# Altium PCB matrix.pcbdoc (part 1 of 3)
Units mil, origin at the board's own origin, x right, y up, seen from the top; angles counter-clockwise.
Board outline 9450 x 9250 mil, 2 copper layers (Top Layer, Bottom Layer); 316 components, 228 nets, 906 pads, 1393 vias.
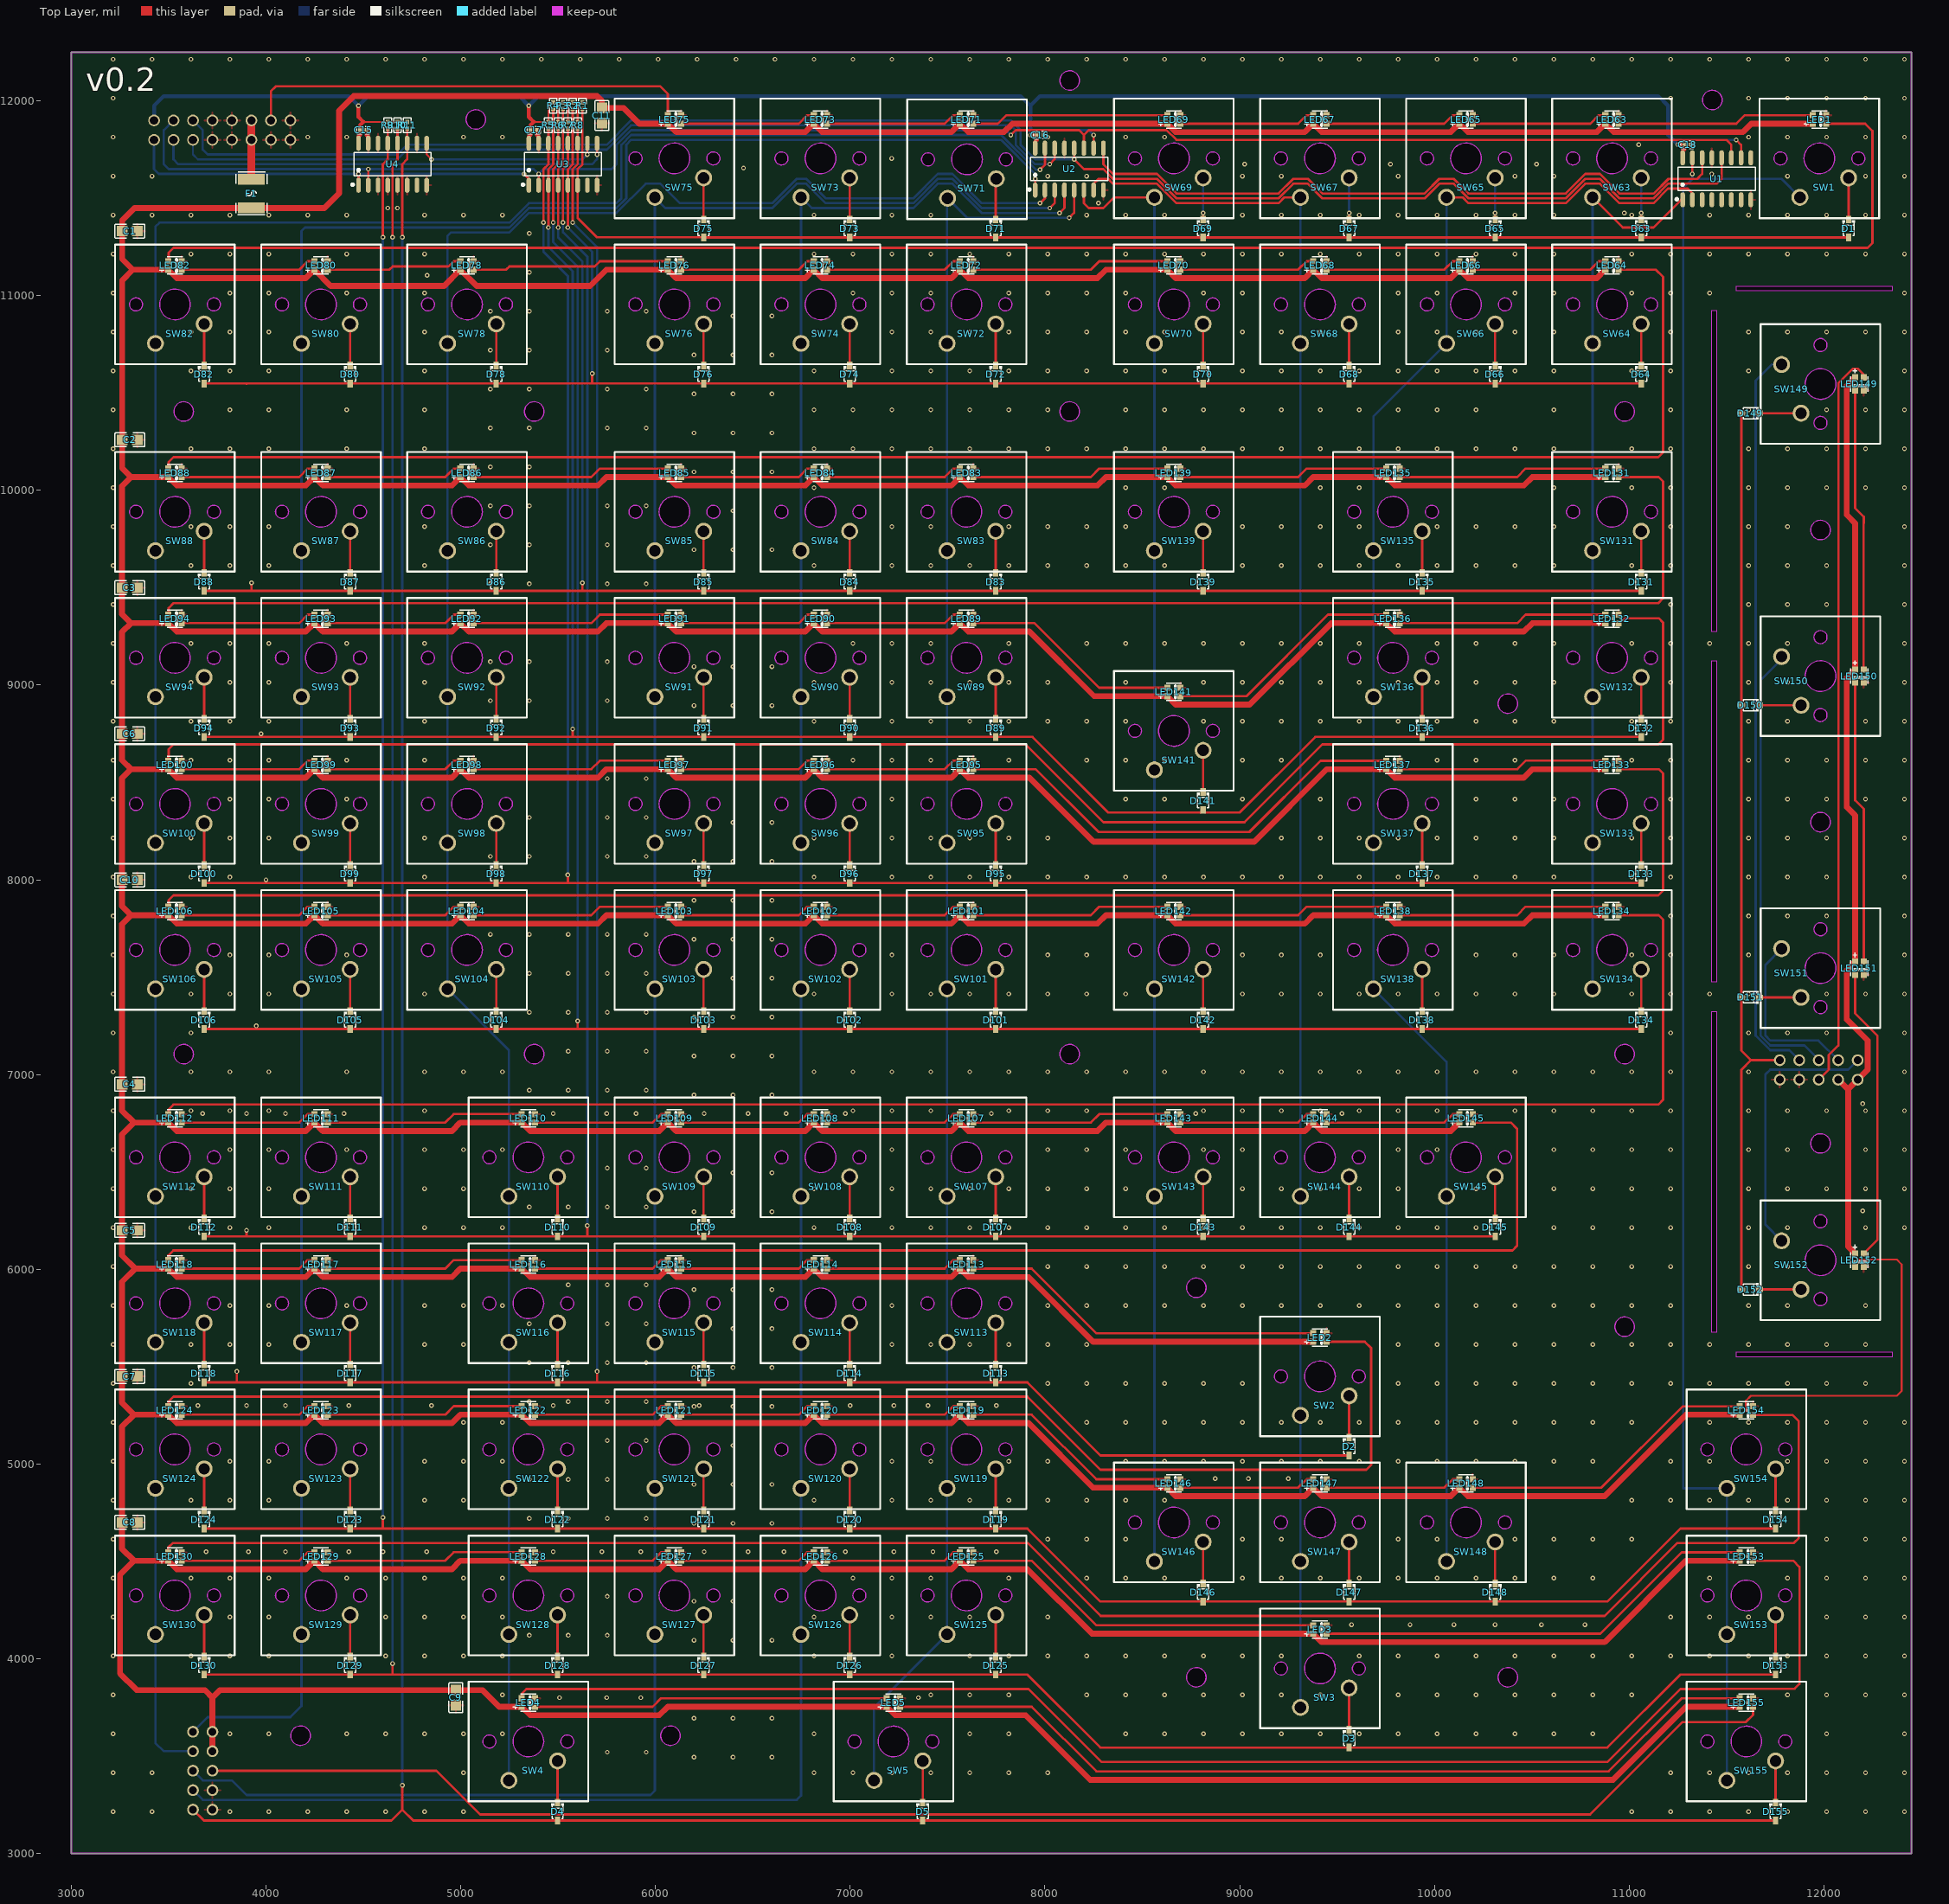
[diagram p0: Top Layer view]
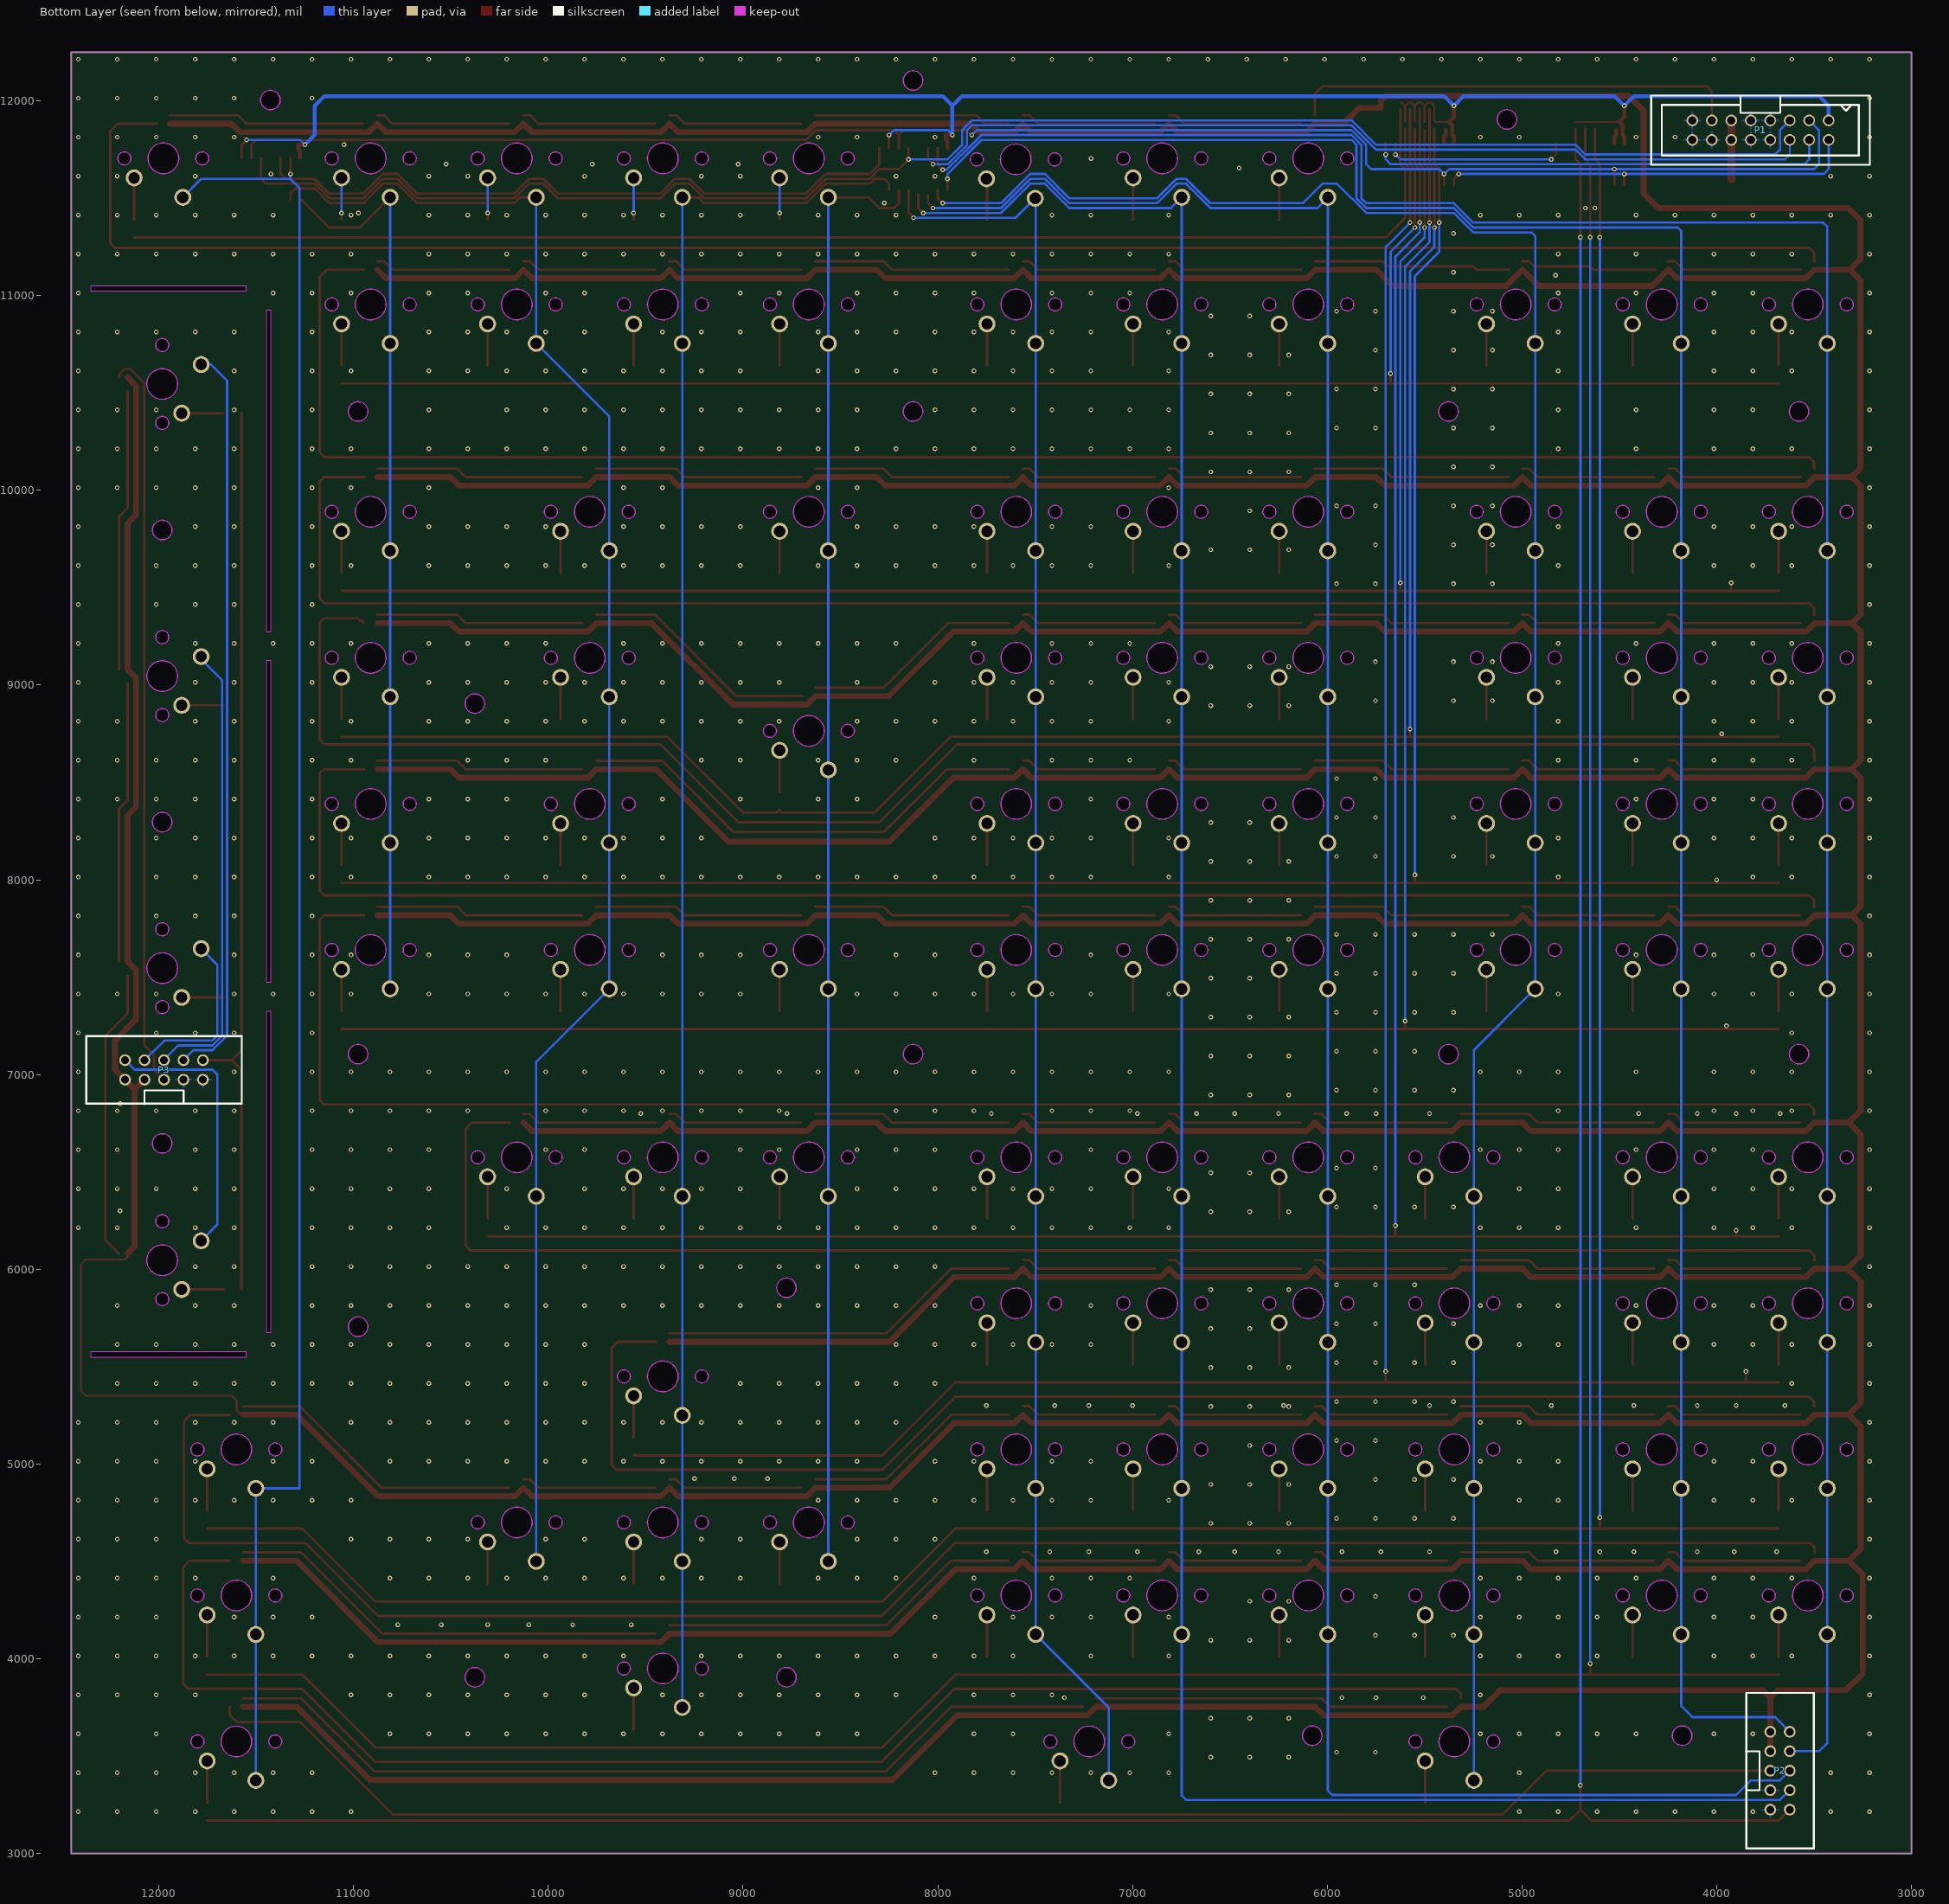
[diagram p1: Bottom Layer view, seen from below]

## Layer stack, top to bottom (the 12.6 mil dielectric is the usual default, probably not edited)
Top Layer: signal copper (thickness not stored)
Dielectric: dielectric 12.6, FR-4, Dk 4.8
Bottom Layer: signal copper (thickness not stored)

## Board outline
3000,12250 12450,12250 12450,3000 3000,3000
cut-out: 12032.9,6646.5 cw(c11982.9,6646.5) 11932.9,6646.5 cw(c11982.9,6646.5)
cut-out: 12032.9,9796.5 cw(c11982.9,9796.5) 11932.9,9796.5 cw(c11982.9,9796.5)
cut-out: 12032.9,8296.5 cw(c11982.9,8296.5) 11932.9,8296.5 cw(c11982.9,8296.5)
cut-out: 10427.3,8905 cw(c10377.3,8905) 10327.3,8905 cw(c10377.3,8905)
cut-out: 6127.3,3605 cw(c6077.3,3605) 6027.3,3605 cw(c6077.3,3605)
cut-out: 8827.3,3905 cw(c8777.3,3905) 8727.3,3905 cw(c8777.3,3905)
cut-out: 8827.3,5905 cw(c8777.3,5905) 8727.3,5905 cw(c8777.3,5905)
cut-out: 11027.3,5705 cw(c10977.3,5705) 10927.3,5705 cw(c10977.3,5705)
cut-out: 10427.3,3905 cw(c10377.3,3905) 10327.3,3905 cw(c10377.3,3905)
cut-out: 5427.3,7105 cw(c5377.3,7105) 5327.3,7105 cw(c5377.3,7105)
cut-out: 5427.3,10405 cw(c5377.3,10405) 5327.3,10405 cw(c5377.3,10405)
cut-out: 8177.3,10405 cw(c8127.3,10405) 8077.3,10405 cw(c8127.3,10405)
cut-out: 8177.3,7105 cw(c8127.3,7105) 8077.3,7105 cw(c8127.3,7105)
cut-out: 11027.3,7105 cw(c10977.3,7105) 10927.3,7105 cw(c10977.3,7105)
cut-out: 11027.3,10405 cw(c10977.3,10405) 10927.3,10405 cw(c10977.3,10405)
cut-out: 4227.3,3605 cw(c4177.3,3605) 4127.3,3605 cw(c4177.3,3605)
cut-out: 3627.3,7105 cw(c3577.3,7105) 3527.3,7105 cw(c3577.3,7105)
cut-out: 8177.3,12105 cw(c8127.3,12105) 8077.3,12105 cw(c8127.3,12105)
cut-out: 11477.3,12005 cw(c11427.3,12005) 11377.3,12005 cw(c11427.3,12005)
cut-out: 3627.3,10405 cw(c3577.3,10405) 3527.3,10405 cw(c3577.3,10405)
cut-out: 5127.3,11905 cw(c5077.3,11905) 5027.3,11905 cw(c5077.3,11905)
cut-out: 11550,11050 12350,11050 12350,11025 11550,11025
cut-out: 11425,10925 11450,10925 11450,9275 11425,9275
cut-out: 11550,5575 12350,5575 12350,5550 11550,5550
cut-out: 11425,9125 11450,9125 11450,7475 11425,7475
cut-out: 11425,7325 11450,7325 11450,5675 11425,5675

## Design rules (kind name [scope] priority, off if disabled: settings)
BoardOutlineClearance copperThickness1oz [All] p0: genericclearance=10 ignorepadtopadclearanceinfootprint=FALSE except(0: Arc-SplitContinuation Track-SplitContinuation SMDPad-SplitContinuation THPad-SplitContinuation Via-SplitContinuation Fill-SplitContinuation Poly-SplitContinuation Region-SplitContinuation Text-SplitContinuation; 6: Track-CutoutEdge SMDPad-CutoutEdge THPad-CutoutEdge Via-CutoutEdge Region-CutoutEdge; 11.8: Track-OutlineEdge SMDPad-OutlineEdge THPad-OutlineEdge Via-OutlineEdge Fill-OutlineEdge Region-OutlineEdge Poly-OutlineEdge Text-OutlineEdge Fill-CutoutEdge)
BoardOutlineClearance copperThickness2oz [All] p0: genericclearance=10 ignorepadtopadclearanceinfootprint=FALSE except(0: Arc-SplitContinuation Track-SplitContinuation SMDPad-SplitContinuation THPad-SplitContinuation Via-SplitContinuation Fill-SplitContinuation Poly-SplitContinuation Region-SplitContinuation Text-SplitContinuation; 6: Track-CutoutEdge SMDPad-CutoutEdge THPad-CutoutEdge Via-CutoutEdge Region-CutoutEdge; 11.8: Track-OutlineEdge SMDPad-OutlineEdge THPad-OutlineEdge Via-OutlineEdge Fill-OutlineEdge Region-OutlineEdge Poly-OutlineEdge Text-OutlineEdge Fill-CutoutEdge)
Clearance copperThickness1oz [(InNet('$1I2620\$1N2306') OR InNet('$1N3668') OR InNet('$1I2664\$1N2306') OR InNet('$1N3676') OR InNet('$1I2730\$1N2306') OR InNet('$1I2752\$1N2306') OR InNet('$1I2774\$1N2306') OR InNet('$1I2796\$1N2306') OR InNet('$1I2818\$1N2306') OR InNet('$1I2840\$1N2306') OR InNet('GND') OR InNet('$1N3658') OR InNet('$1N3656') OR InNet('$1N3660') OR InNet('$1N3654') OR InNet('$1N3662') OR InNet('$1N3652') OR InNet('$1N3664') OR InNet('$1N3698') OR InNet('$1N3688') OR InNet('$1N3683') OR InNet('$1N7005') OR InNet('$1N7024') OR InNet('$1N4304') OR InNet('$1N7019') OR InNet('$1N7386') OR InNet('$1I6691\$1N2306') OR InNet('$1I6735\$1N2306') OR InNet('$1N7722') OR InNet('$1I6783\$1N2306') OR InNet('$1I6893\$1N2306') OR InNet('$1I4022\$1N2306') OR InNet('$1I4044\$1N2306') OR InNet('$1I4066\$1N2306') OR InNet('$1I4088\$1N2306') OR InNet('$1I4110\$1N2306') OR InNet('$1I4132\$1N2306') OR InNet('$1I4184\$1N2306') OR InNet('$1I4228\$1N2306') OR InNet('$1I4272\$1N2306') OR InNet('$1I4438\$1N2306') OR InNet('$1I4460\$1N2306') OR InNet('$1I4482\$1N2306') OR InNet('$1I4504\$1N2306') OR InNet('$1I4526\$1N2306') OR InNet('$1I4548\$1N2306') OR InNet('$1I4578\$1N2306') OR InNet('$1I4600\$1N2306') OR InNet('$1I4622\$1N2306') OR InNet('$1I4644\$1N2306') OR InNet('$1I4666\$1N2306') OR InNet('$1I4688\$1N2306') OR InNet('$1I4718\$1N2306') OR InNet('$1I4740\$1N2306') OR InNet('$1I4762\$1N2306') OR InNet('$1I4784\$1N2306') OR InNet('$1I4806\$1N2306') OR InNet('$1I4828\$1N2306') OR InNet('$1I4858\$1N2306') OR InNet('$1I4880\$1N2306') OR InNet('$1I4902\$1N2306') OR InNet('$1I4924\$1N2306') OR InNet('$1I4946\$1N2306') OR InNet('$1I4968\$1N2306') OR InNet('$1I4998\$1N2306') OR InNet('$1N7677') OR InNet('$1I5020\$1N2306') OR InNet('$1I5042\$1N2306') OR InNet('$1I5064\$1N2306') OR InNet('$1I5086\$1N2306') OR InNet('$1I5108\$1N2306') OR InNet('$1I5424\$1N2306') OR InNet('$1N7690') OR InNet('$1I5446\$1N2306') OR InNet('$1I5468\$1N2306') OR InNet('$1I5490\$1N2306') OR InNet('$1I5512\$1N2306') OR InNet('$1I5534\$1N2306') OR InNet('$1I5566\$1N2306') OR InNet('$1I5588\$1N2306') OR InNet('$1I5610\$1N2306') OR InNet('$1I5632\$1N2306') OR InNet('$1I5654\$1N2306') OR InNet('$1I5676\$1N2306') OR InNet('$1I5708\$1N2306') OR InNet('$1I5730\$1N2306') OR InNet('$1I5752\$1N2306') OR InNet('$1I5774\$1N2306') OR InNet('$1I5796\$1N2306') OR InNet('$1I5818\$1N2306') OR InNet('$1I6023\$1N2306') OR InNet('$1I6045\$1N2306') OR InNet('$1I6067\$1N2306') OR InNet('$1I6089\$1N2306') OR InNet('$1I6177\$1N2306') OR InNet('$1I6155\$1N2306') OR InNet('$1I6221\$1N2306') OR InNet('$1I6199\$1N2306') OR InNet('$1I6243\$1N2306') OR InNet('$1I6287\$1N2306') OR InNet('$1I6309\$1N2306') OR InNet('$1I6507\$1N2306') OR InNet('$1I6529\$1N2306') OR InNet('$1I6553\$1N2306') OR InNet('$1I6621\$1N2306') OR InNet('$1I6643\$1N2306') OR InNet('$1I6665\$1N2306') OR InNet('$1I6805\$1N2306') OR InNet('$1I6827\$1N2306') OR InNet('$1I6849\$1N2306') OR InNet('$1I6871\$1N2306') OR InNet('$1I6915\$1N2306') OR InNet('$1I6959\$1N2306') OR InNet('$1I6981\$1N2306') OR InNet('$1N7185') OR InNet('$1N7239') OR InNet('$1N4154') OR InNet('$1N4156') OR InNet('$1N4158') OR InNet('$1N4160') OR InNet('$1N7014') OR InNet('$1N4296') OR InNet('$1N4300') OR InNet('$1N4570') OR InNet('$1N7039') OR InNet('$1N4572') OR InNet('$1N7034') OR InNet('$1N4574') OR InNet('$1N4576') OR InNet('$1N4710') OR InNet('$1N4712') OR InNet('$1N7064') OR InNet('$1N4714') OR InNet('$1N4716') OR InNet('$1N7054') OR InNet('$1N4850') OR InNet('$1N4852') OR InNet('$1N7093') OR InNet('$1N4854') OR InNet('$1N4856') OR InNet('$1N4990') OR InNet('$1N7141') OR InNet('$1N4992') OR InNet('$1N7136') OR InNet('$1N4994') OR InNet('$1N4996') OR InNet('$1N7126') OR InNet('$1N5130') OR InNet('$1N7163') OR InNet('$1N5132') OR InNet('$1N5138') OR InNet('$1N5134') OR InNet('$1N5136') OR InNet('$1N7156') OR InNet('$1N5556') OR InNet('$1N7178') OR InNet('$1N5558') OR InNet('$1N5564') OR InNet('$1N5560') OR InNet('$1N5562') OR InNet('$1N7168') OR InNet('$1N5698') OR InNet('$1N5700') OR InNet('$1N5706') OR InNet('$1N5702') OR InNet('$1N5704') OR InNet('$1N5840') OR InNet('$1N7211') OR InNet('$1N5842') OR InNet('$1N5848') OR InNet('$1N5844') OR InNet('$1N5846') OR InNet('$1N7049') OR InNet('$1N7074') OR InNet('$1N7122') OR InNet('$1N7151') OR InNet('$1N7044') OR InNet('$1N7146') OR InNet('$1N6551') OR InNet('$1N6575') OR InNet('$1N6687') OR InNet('$1N6689') OR InNet('$1N7217') OR InNet('$1I6871\DO') OR InNet('$1I2686\$1N2306') OR InNet('$1N7861') OR InNet('$1N7870') OR InNet('$1N7950') OR InNet('$1N7845') OR InNet('$1N7875') OR InNet('$1N8092') OR InNet('$1N8084') OR InNet('$1N8347') OR InNet('$1N8062') OR InNet('$1N8140') OR InNet('$1N8764') OR InNet('$1N8766') OR InNet('$1N8768') OR InNet('$1N8772') OR InNet('3V3') OR InNet('$1N12570') OR InNet('$1N14585') OR InNet('$1N12677') OR InNet('$1N14611') OR InNet('LED') OR InNet('$1N19321') OR InNet('$1N19760') OR InNet('$1N15532') OR InNet('$1N17072') OR InNet('$1N19444') OR InNet('$1N19455') OR InNet('$1N19463') OR InNet('$1N19459') OR InNet('5V') OR InNet('$1N16554') OR InNet('SCK') OR InNet('ROWS') OR InNet('COLS') OR InNet('ROWL') OR InNet('COLL') OR InNet('$1N17492') OR InNet('$1N21463') OR InNet('$1N21690') OR InNet('$1N21742') OR InNet('$1N21793') OR InNet('$1N21809') OR InNet('$1N22008') OR InNet('$1N28901'))] p1: gap=7 ignorepadtopadclearanceinfootprint=FALSE except(4: Track-Track; 6: Track-SMDPad SMDPad-SMDPad Track-THPad SMDPad-THPad THPad-THPad Track-Via SMDPad-Via THPad-Via Via-Via SMDPad-Fill THPad-Fill Via-Fill Fill-Fill Track-Region SMDPad-Region THPad-Region Via-Region Region-Region Track-Poly SMDPad-Poly THPad-Poly Via-Poly Fill-Poly Region-Poly Poly-Poly Track-Text SMDPad-Text THPad-Text Via-Text Fill-Text Region-Text Poly-Text Text-Text; 6.9: Track-Hole SMDPad-Hole THPad-Hole Via-Hole Fill-Hole Region-Hole Poly-Hole Text-Hole Sheet-Hole; 11.8: Track-Fill Fill-Region Track-Sheet SMDPad-Sheet THPad-Sheet Via-Sheet Fill-Sheet Region-Sheet Poly-Sheet Text-Sheet)
Clearance copperThickness2oz [All] p1: gap=7 ignorepadtopadclearanceinfootprint=FALSE except(6: Track-SMDPad SMDPad-SMDPad Track-THPad SMDPad-THPad THPad-THPad Track-Via SMDPad-Via THPad-Via Via-Via SMDPad-Fill THPad-Fill Via-Fill Fill-Fill Track-Region SMDPad-Region THPad-Region Via-Region Region-Region Track-Poly SMDPad-Poly THPad-Poly Via-Poly Fill-Poly Region-Poly Poly-Poly Track-Text SMDPad-Text THPad-Text Via-Text Fill-Text Region-Text Poly-Text Text-Text; 6.9: Track-Hole SMDPad-Hole THPad-Hole Via-Hole Fill-Hole Region-Hole Poly-Hole Text-Hole Sheet-Hole; 8: Track-Track; 11.8: Track-Fill Fill-Region Track-Sheet SMDPad-Sheet THPad-Sheet Via-Sheet Fill-Sheet Region-Sheet Poly-Sheet Text-Sheet)
DiffPairsRouting differentialPair [All] p1: maxuncoupledlength=10 minlimit=6 maxlimit=6 mostfreqgap=6 toplayer_minwidth=5 toplayer_prefwidth=10 toplayer_maxwidth=100 bottomlayer_minwidth=5 bottomlayer_prefwidth=10 bottomlayer_maxwidth=100
PasteMaskExpansion pasteMaskExpansion [All] p1: expansion=0
PlaneConnect innerPlane [All] p1: planeconnectstyle=Relief reliefexpansion=20 reliefentries=4 reliefconductorwidth=10 reliefairgap=10
PolygonConnect copperRegion [All] p1: connectstyle=Relief reliefentries=4 reliefconductorwidth=10 polygonreliefangle="90 Angle" airgapwidth=10
RoutingVias viaSize [All] p1: viastyle="Through Hole" holewidth=12.0078 minholewidth=11.811 maxholewidth=248.0314 width=24.0158 minwidth=19.685 maxwidth=393.7008
SolderMaskExpansion solderMaskExpansion [All] p1: useseparateexpansions=TRUE expansion=2 expansionbottom=2
Width copperThickness1oz [All] p1: maxlimit=100 minlimit=5 preferedwidth=10
Width copperThickness2oz [All] p1: maxlimit=100 minlimit=8 preferedwidth=10

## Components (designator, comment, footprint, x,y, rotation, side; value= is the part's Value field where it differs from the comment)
C1 "CL21A106KAYNNNE_C15850" C0805 3300.31,11331.5 r180 top locked
C2 "CL21A106KAYNNNE_C15850" C0805 3300.31,10259.66 r180 top locked
C3 "CL21A106KAYNNNE_C15850" C0805 3300,9500 r0 top locked
C4 "CL21A106KAYNNNE_C15850" C0805 3300,6950 r180 top locked
C5 "CL21A106KAYNNNE_C15850" C0805 3300,6200 r180 top locked
C6 "CL21A106KAYNNNE_C15850" C0805 3300,8750 r180 top locked
C7 "CL21A106KAYNNNE_C15850" C0805 3300,5450 r180 top locked
C8 "CL21A106KAYNNNE_C15850" C0805 3300,4700 r180 top locked
C9 "CL21A106KAYNNNE_C15850" C0805 4975,3800 r90 top locked
C10 "CL21A106KAYNNNE_C15850" C0805 3300,8000 r180 top locked
C11 "CL21A106KAYNNNE_C15850" C0805 5725,11925 r90 top locked
C15 "CL05B104KO5NNNC" C0402 4500,11850 r180 top locked
C16 "CL05B104KO5NNNC" C0402 7975,11825 r180 top locked
C17 "CL05B104KO5NNNC" C0402 5375,11850 r180 top locked
C18 "CL05B104KO5NNNC" C0402 11300,11775 r180 top locked
D1 "1N4148WS_C2128" SOD-323_L1.8-W1.3-LS2.5-RD 12127.29,11344.97 r270 top locked
D2 "1N4148WS_C2128" SOD-323_L1.8-W1.3-LS2.5-RD 9562.29,5089.97 r270 top locked
D3 "1N4148WS_C2128" SOD-323_L1.8-W1.3-LS2.5-RD 9562.29,3589.97 r270 top locked
D4 "1N4148WS_C2128" SOD-323_L1.8-W1.3-LS2.5-RD 5497.29,3214.97 r270 top locked
D5 "1N4148WS_C2128" SOD-323_L1.8-W1.3-LS2.5-RD 7372.29,3214.97 r270 top locked
D63 "1N4148WS_C2128" SOD-323_L1.8-W1.3-LS2.5-RD 11062.29,11344.97 r270 top locked
D64 "1N4148WS_C2128" SOD-323_L1.8-W1.3-LS2.5-RD 11062.29,10594.97 r270 top locked
D65 "1N4148WS_C2128" SOD-323_L1.8-W1.3-LS2.5-RD 10312.29,11344.97 r270 top locked
D66 "1N4148WS_C2128" SOD-323_L1.8-W1.3-LS2.5-RD 10312.29,10594.97 r270 top locked
D67 "1N4148WS_C2128" SOD-323_L1.8-W1.3-LS2.5-RD 9562.29,11344.97 r270 top locked
D68 "1N4148WS_C2128" SOD-323_L1.8-W1.3-LS2.5-RD 9562.29,10594.97 r270 top locked
D69 "1N4148WS_C2128" SOD-323_L1.8-W1.3-LS2.5-RD 8812.29,11344.97 r270 top locked
D70 "1N4148WS_C2128" SOD-323_L1.8-W1.3-LS2.5-RD 8812.29,10594.97 r270 top locked
D71 "1N4148WS_C2128" SOD-323_L1.8-W1.3-LS2.5-RD 7747.29,11344.97 r270 top locked
D72 "1N4148WS_C2128" SOD-323_L1.8-W1.3-LS2.5-RD 7747.29,10594.97 r270 top locked
D73 "1N4148WS_C2128" SOD-323_L1.8-W1.3-LS2.5-RD 6997.29,11344.97 r270 top locked
D74 "1N4148WS_C2128" SOD-323_L1.8-W1.3-LS2.5-RD 6997.29,10594.97 r270 top locked
D75 "1N4148WS_C2128" SOD-323_L1.8-W1.3-LS2.5-RD 6247.29,11344.97 r270 top locked
D76 "1N4148WS_C2128" SOD-323_L1.8-W1.3-LS2.5-RD 6247.29,10594.97 r270 top locked
D78 "1N4148WS_C2128" SOD-323_L1.8-W1.3-LS2.5-RD 5182.29,10594.97 r270 top locked
D80 "1N4148WS_C2128" SOD-323_L1.8-W1.3-LS2.5-RD 4432.29,10594.97 r270 top locked
D82 "1N4148WS_C2128" SOD-323_L1.8-W1.3-LS2.5-RD 3682.29,10594.97 r270 top locked
D83 "1N4148WS_C2128" SOD-323_L1.8-W1.3-LS2.5-RD 7747.29,9529.97 r270 top locked
D84 "1N4148WS_C2128" SOD-323_L1.8-W1.3-LS2.5-RD 6997.29,9529.97 r270 top locked
D85 "1N4148WS_C2128" SOD-323_L1.8-W1.3-LS2.5-RD 6247.29,9529.97 r270 top locked
D86 "1N4148WS_C2128" SOD-323_L1.8-W1.3-LS2.5-RD 5182.29,9529.97 r270 top locked
D87 "1N4148WS_C2128" SOD-323_L1.8-W1.3-LS2.5-RD 4432.29,9529.97 r270 top locked
D88 "1N4148WS_C2128" SOD-323_L1.8-W1.3-LS2.5-RD 3682.29,9529.97 r270 top locked
D89 "1N4148WS_C2128" SOD-323_L1.8-W1.3-LS2.5-RD 7747.29,8779.97 r270 top locked
D90 "1N4148WS_C2128" SOD-323_L1.8-W1.3-LS2.5-RD 6997.29,8779.97 r270 top locked
D91 "1N4148WS_C2128" SOD-323_L1.8-W1.3-LS2.5-RD 6247.29,8779.97 r270 top locked
D92 "1N4148WS_C2128" SOD-323_L1.8-W1.3-LS2.5-RD 5182.29,8779.97 r270 top locked
D93 "1N4148WS_C2128" SOD-323_L1.8-W1.3-LS2.5-RD 4432.29,8779.97 r270 top locked
D94 "1N4148WS_C2128" SOD-323_L1.8-W1.3-LS2.5-RD 3682.29,8779.97 r270 top locked
D95 "1N4148WS_C2128" SOD-323_L1.8-W1.3-LS2.5-RD 7747.29,8029.97 r270 top locked
D96 "1N4148WS_C2128" SOD-323_L1.8-W1.3-LS2.5-RD 6997.29,8029.97 r270 top locked
D97 "1N4148WS_C2128" SOD-323_L1.8-W1.3-LS2.5-RD 6247.29,8029.97 r270 top locked
D98 "1N4148WS_C2128" SOD-323_L1.8-W1.3-LS2.5-RD 5182.29,8029.97 r270 top locked
D99 "1N4148WS_C2128" SOD-323_L1.8-W1.3-LS2.5-RD 4432.29,8029.97 r270 top locked
D100 "1N4148WS_C2128" SOD-323_L1.8-W1.3-LS2.5-RD 3682.29,8029.97 r270 top locked
D101 "1N4148WS_C2128" SOD-323_L1.8-W1.3-LS2.5-RD 7747.29,7279.97 r270 top locked
D102 "1N4148WS_C2128" SOD-323_L1.8-W1.3-LS2.5-RD 6997.29,7279.97 r270 top locked
D103 "1N4148WS_C2128" SOD-323_L1.8-W1.3-LS2.5-RD 6247.29,7279.97 r270 top locked
D104 "1N4148WS_C2128" SOD-323_L1.8-W1.3-LS2.5-RD 5182.29,7279.97 r270 top locked
D105 "1N4148WS_C2128" SOD-323_L1.8-W1.3-LS2.5-RD 4432.29,7279.97 r270 top locked
D106 "1N4148WS_C2128" SOD-323_L1.8-W1.3-LS2.5-RD 3682.29,7279.97 r270 top locked
D107 "1N4148WS_C2128" SOD-323_L1.8-W1.3-LS2.5-RD 7747.29,6214.97 r270 top locked
D108 "1N4148WS_C2128" SOD-323_L1.8-W1.3-LS2.5-RD 6997.29,6214.97 r270 top locked
D109 "1N4148WS_C2128" SOD-323_L1.8-W1.3-LS2.5-RD 6247.29,6214.97 r270 top locked
D110 "1N4148WS_C2128" SOD-323_L1.8-W1.3-LS2.5-RD 5497.29,6214.97 r270 top locked
D111 "1N4148WS_C2128" SOD-323_L1.8-W1.3-LS2.5-RD 4432.29,6214.97 r270 top locked
D112 "1N4148WS_C2128" SOD-323_L1.8-W1.3-LS2.5-RD 3682.29,6214.97 r270 top locked
D113 "1N4148WS_C2128" SOD-323_L1.8-W1.3-LS2.5-RD 7747.29,5464.97 r270 top locked
D114 "1N4148WS_C2128" SOD-323_L1.8-W1.3-LS2.5-RD 6997.29,5464.97 r270 top locked
D115 "1N4148WS_C2128" SOD-323_L1.8-W1.3-LS2.5-RD 6247.29,5464.97 r270 top locked
D116 "1N4148WS_C2128" SOD-323_L1.8-W1.3-LS2.5-RD 5497.29,5464.97 r270 top locked
D117 "1N4148WS_C2128" SOD-323_L1.8-W1.3-LS2.5-RD 4432.29,5464.97 r270 top locked
D118 "1N4148WS_C2128" SOD-323_L1.8-W1.3-LS2.5-RD 3682.29,5464.97 r270 top locked
D119 "1N4148WS_C2128" SOD-323_L1.8-W1.3-LS2.5-RD 7747.29,4714.97 r270 top locked
D120 "1N4148WS_C2128" SOD-323_L1.8-W1.3-LS2.5-RD 6997.29,4714.97 r270 top locked
D121 "1N4148WS_C2128" SOD-323_L1.8-W1.3-LS2.5-RD 6247.29,4714.97 r270 top locked
D122 "1N4148WS_C2128" SOD-323_L1.8-W1.3-LS2.5-RD 5497.29,4714.97 r270 top locked
D123 "1N4148WS_C2128" SOD-323_L1.8-W1.3-LS2.5-RD 4432.29,4714.97 r270 top locked
D124 "1N4148WS_C2128" SOD-323_L1.8-W1.3-LS2.5-RD 3682.29,4714.97 r270 top locked
D125 "1N4148WS_C2128" SOD-323_L1.8-W1.3-LS2.5-RD 7747.29,3964.97 r270 top locked
D126 "1N4148WS_C2128" SOD-323_L1.8-W1.3-LS2.5-RD 6997.29,3964.97 r270 top locked
D127 "1N4148WS_C2128" SOD-323_L1.8-W1.3-LS2.5-RD 6247.29,3964.97 r270 top locked
D128 "1N4148WS_C2128" SOD-323_L1.8-W1.3-LS2.5-RD 5497.29,3964.97 r270 top locked
D129 "1N4148WS_C2128" SOD-323_L1.8-W1.3-LS2.5-RD 4432.29,3964.97 r270 top locked
D130 "1N4148WS_C2128" SOD-323_L1.8-W1.3-LS2.5-RD 3682.29,3964.97 r270 top locked
D131 "1N4148WS_C2128" SOD-323_L1.8-W1.3-LS2.5-RD 11062.29,9529.97 r270 top locked
D132 "1N4148WS_C2128" SOD-323_L1.8-W1.3-LS2.5-RD 11062.29,8779.97 r270 top locked
D133 "1N4148WS_C2128" SOD-323_L1.8-W1.3-LS2.5-RD 11062.29,8029.97 r270 top locked
D134 "1N4148WS_C2128" SOD-323_L1.8-W1.3-LS2.5-RD 11062.29,7279.97 r270 top locked
D135 "1N4148WS_C2128" SOD-323_L1.8-W1.3-LS2.5-RD 9937.29,9529.97 r270 top locked
D136 "1N4148WS_C2128" SOD-323_L1.8-W1.3-LS2.5-RD 9937.29,8779.97 r270 top locked
D137 "1N4148WS_C2128" SOD-323_L1.8-W1.3-LS2.5-RD 9937.29,8029.97 r270 top locked
D138 "1N4148WS_C2128" SOD-323_L1.8-W1.3-LS2.5-RD 9937.29,7279.97 r270 top locked
D139 "1N4148WS_C2128" SOD-323_L1.8-W1.3-LS2.5-RD 8812.29,9529.97 r270 top locked
D141 "1N4148WS_C2128" SOD-323_L1.8-W1.3-LS2.5-RD 8812.29,8404.97 r270 top locked
D142 "1N4148WS_C2128" SOD-323_L1.8-W1.3-LS2.5-RD 8812.29,7279.97 r270 top locked
D143 "1N4148WS_C2128" SOD-323_L1.8-W1.3-LS2.5-RD 8812.29,6214.97 r270 top locked
D144 "1N4148WS_C2128" SOD-323_L1.8-W1.3-LS2.5-RD 9562.29,6214.97 r270 top locked
D145 "1N4148WS_C2128" SOD-323_L1.8-W1.3-LS2.5-RD 10312.29,6214.97 r270 top locked
D146 "1N4148WS_C2128" SOD-323_L1.8-W1.3-LS2.5-RD 8812.29,4339.97 r270 top locked
D147 "1N4148WS_C2128" SOD-323_L1.8-W1.3-LS2.5-RD 9562.29,4339.97 r270 top locked
D148 "1N4148WS_C2128" SOD-323_L1.8-W1.3-LS2.5-RD 10312.29,4339.97 r270 top locked
D149 "1N4148WS_C2128" SOD-323_L1.8-W1.3-LS2.5-RD 11622.91,10396.45 r180 top locked
D150 "1N4148WS_C2128" SOD-323_L1.8-W1.3-LS2.5-RD 11622.91,8896.45 r180 top locked
D151 "1N4148WS_C2128" SOD-323_L1.8-W1.3-LS2.5-RD 11622.91,7396.45 r180 top locked
D152 "1N4148WS_C2128" SOD-323_L1.8-W1.3-LS2.5-RD 11622.91,5896.45 r180 top locked
D153 "1N4148WS_C2128" SOD-323_L1.8-W1.3-LS2.5-RD 11752.29,3964.97 r270 top locked
D154 "1N4148WS_C2128" SOD-323_L1.8-W1.3-LS2.5-RD 11752.29,4714.97 r270 top locked
D155 "1N4148WS_C2128" SOD-323_L1.8-W1.3-LS2.5-RD 11752.29,3214.97 r270 top locked
F1 "1812L150/24MR" F1812 3925,11525 r270 top locked
LED1 "WS2812B-2020-V6" LED-SMD_4P-L2.2-W2.0-P1.00_WS2815C-2020-4P 11977.29,11904.98 r180 top locked
LED2 "WS2812B-2020-V6" LED-SMD_4P-L2.2-W2.0-P1.00_WS2815C-2020-4P 9412.29,5649.98 r180 top locked
LED3 "WS2812B-2020-V6" LED-SMD_4P-L2.2-W2.0-P1.00_WS2815C-2020-4P 9412.29,4149.98 r180 top locked
LED4 "WS2812B-2020-V6" LED-SMD_4P-L2.2-W2.0-P1.00_WS2815C-2020-4P 5347.29,3774.98 r180 top locked
LED5 "WS2812B-2020-V6" LED-SMD_4P-L2.2-W2.0-P1.00_WS2815C-2020-4P 7222.29,3774.98 r180 top locked
LED63 "WS2812B-2020-V6" LED-SMD_4P-L2.2-W2.0-P1.00_WS2815C-2020-4P 10912.29,11904.98 r180 top locked
LED64 "WS2812B-2020-V6" LED-SMD_4P-L2.2-W2.0-P1.00_WS2815C-2020-4P 10912.29,11154.98 r180 top locked
LED65 "WS2812B-2020-V6" LED-SMD_4P-L2.2-W2.0-P1.00_WS2815C-2020-4P 10162.29,11904.98 r180 top locked
LED66 "WS2812B-2020-V6" LED-SMD_4P-L2.2-W2.0-P1.00_WS2815C-2020-4P 10162.29,11154.98 r180 top locked
LED67 "WS2812B-2020-V6" LED-SMD_4P-L2.2-W2.0-P1.00_WS2815C-2020-4P 9412.29,11904.98 r180 top locked
LED68 "WS2812B-2020-V6" LED-SMD_4P-L2.2-W2.0-P1.00_WS2815C-2020-4P 9412.29,11154.98 r180 top locked
LED69 "WS2812B-2020-V6" LED-SMD_4P-L2.2-W2.0-P1.00_WS2815C-2020-4P 8662.29,11904.98 r180 top locked
LED70 "WS2812B-2020-V6" LED-SMD_4P-L2.2-W2.0-P1.00_WS2815C-2020-4P 8662.29,11154.98 r180 top locked
LED71 "WS2812B-2020-V6" LED-SMD_4P-L2.2-W2.0-P1.00_WS2815C-2020-4P 7597.29,11904.98 r180 top locked
LED72 "WS2812B-2020-V6" LED-SMD_4P-L2.2-W2.0-P1.00_WS2815C-2020-4P 7597.29,11154.98 r180 top locked
LED73 "WS2812B-2020-V6" LED-SMD_4P-L2.2-W2.0-P1.00_WS2815C-2020-4P 6847.29,11904.98 r180 top locked
LED74 "WS2812B-2020-V6" LED-SMD_4P-L2.2-W2.0-P1.00_WS2815C-2020-4P 6847.29,11154.98 r180 top locked
LED75 "WS2812B-2020-V6" LED-SMD_4P-L2.2-W2.0-P1.00_WS2815C-2020-4P 6097.29,11904.98 r180 top locked
LED76 "WS2812B-2020-V6" LED-SMD_4P-L2.2-W2.0-P1.00_WS2815C-2020-4P 6097.29,11154.98 r180 top locked
LED78 "WS2812B-2020-V6" LED-SMD_4P-L2.2-W2.0-P1.00_WS2815C-2020-4P 5032.29,11154.98 r180 top locked
LED80 "WS2812B-2020-V6" LED-SMD_4P-L2.2-W2.0-P1.00_WS2815C-2020-4P 4282.29,11154.98 r180 top locked
LED82 "WS2812B-2020-V6" LED-SMD_4P-L2.2-W2.0-P1.00_WS2815C-2020-4P 3532.29,11154.98 r180 top locked
LED83 "WS2812B-2020-V6" LED-SMD_4P-L2.2-W2.0-P1.00_WS2815C-2020-4P 7597.29,10089.98 r180 top locked
LED84 "WS2812B-2020-V6" LED-SMD_4P-L2.2-W2.0-P1.00_WS2815C-2020-4P 6847.29,10089.98 r180 top locked
LED85 "WS2812B-2020-V6" LED-SMD_4P-L2.2-W2.0-P1.00_WS2815C-2020-4P 6097.29,10089.98 r180 top locked
LED86 "WS2812B-2020-V6" LED-SMD_4P-L2.2-W2.0-P1.00_WS2815C-2020-4P 5032.29,10089.98 r180 top locked
LED87 "WS2812B-2020-V6" LED-SMD_4P-L2.2-W2.0-P1.00_WS2815C-2020-4P 4282.29,10089.98 r180 top locked
LED88 "WS2812B-2020-V6" LED-SMD_4P-L2.2-W2.0-P1.00_WS2815C-2020-4P 3532.29,10089.98 r180 top locked
LED89 "WS2812B-2020-V6" LED-SMD_4P-L2.2-W2.0-P1.00_WS2815C-2020-4P 7597.29,9339.98 r180 top locked
LED90 "WS2812B-2020-V6" LED-SMD_4P-L2.2-W2.0-P1.00_WS2815C-2020-4P 6847.29,9339.98 r180 top locked
LED91 "WS2812B-2020-V6" LED-SMD_4P-L2.2-W2.0-P1.00_WS2815C-2020-4P 6097.29,9339.98 r180 top locked
LED92 "WS2812B-2020-V6" LED-SMD_4P-L2.2-W2.0-P1.00_WS2815C-2020-4P 5032.29,9339.98 r180 top locked
LED93 "WS2812B-2020-V6" LED-SMD_4P-L2.2-W2.0-P1.00_WS2815C-2020-4P 4282.29,9339.98 r180 top locked
LED94 "WS2812B-2020-V6" LED-SMD_4P-L2.2-W2.0-P1.00_WS2815C-2020-4P 3532.29,9339.98 r180 top locked
LED95 "WS2812B-2020-V6" LED-SMD_4P-L2.2-W2.0-P1.00_WS2815C-2020-4P 7597.29,8589.98 r180 top locked
LED96 "WS2812B-2020-V6" LED-SMD_4P-L2.2-W2.0-P1.00_WS2815C-2020-4P 6847.29,8589.98 r180 top locked
LED97 "WS2812B-2020-V6" LED-SMD_4P-L2.2-W2.0-P1.00_WS2815C-2020-4P 6097.29,8589.98 r180 top locked
LED98 "WS2812B-2020-V6" LED-SMD_4P-L2.2-W2.0-P1.00_WS2815C-2020-4P 5032.29,8589.98 r180 top locked
LED99 "WS2812B-2020-V6" LED-SMD_4P-L2.2-W2.0-P1.00_WS2815C-2020-4P 4282.29,8589.98 r180 top locked
LED100 "WS2812B-2020-V6" LED-SMD_4P-L2.2-W2.0-P1.00_WS2815C-2020-4P 3532.29,8589.98 r180 top locked
LED101 "WS2812B-2020-V6" LED-SMD_4P-L2.2-W2.0-P1.00_WS2815C-2020-4P 7597.29,7839.98 r180 top locked
LED102 "WS2812B-2020-V6" LED-SMD_4P-L2.2-W2.0-P1.00_WS2815C-2020-4P 6847.29,7839.98 r180 top locked
LED103 "WS2812B-2020-V6" LED-SMD_4P-L2.2-W2.0-P1.00_WS2815C-2020-4P 6097.29,7839.98 r180 top locked
LED104 "WS2812B-2020-V6" LED-SMD_4P-L2.2-W2.0-P1.00_WS2815C-2020-4P 5032.29,7839.98 r180 top locked
LED105 "WS2812B-2020-V6" LED-SMD_4P-L2.2-W2.0-P1.00_WS2815C-2020-4P 4282.29,7839.98 r180 top locked
LED106 "WS2812B-2020-V6" LED-SMD_4P-L2.2-W2.0-P1.00_WS2815C-2020-4P 3532.29,7839.98 r180 top locked
LED107 "WS2812B-2020-V6" LED-SMD_4P-L2.2-W2.0-P1.00_WS2815C-2020-4P 7597.29,6774.98 r180 top locked
LED108 "WS2812B-2020-V6" LED-SMD_4P-L2.2-W2.0-P1.00_WS2815C-2020-4P 6847.29,6774.98 r180 top locked
LED109 "WS2812B-2020-V6" LED-SMD_4P-L2.2-W2.0-P1.00_WS2815C-2020-4P 6097.29,6774.98 r180 top locked
LED110 "WS2812B-2020-V6" LED-SMD_4P-L2.2-W2.0-P1.00_WS2815C-2020-4P 5347.29,6774.98 r180 top locked
LED111 "WS2812B-2020-V6" LED-SMD_4P-L2.2-W2.0-P1.00_WS2815C-2020-4P 4282.29,6774.98 r180 top locked
LED112 "WS2812B-2020-V6" LED-SMD_4P-L2.2-W2.0-P1.00_WS2815C-2020-4P 3532.29,6774.98 r180 top locked
LED113 "WS2812B-2020-V6" LED-SMD_4P-L2.2-W2.0-P1.00_WS2815C-2020-4P 7597.29,6024.98 r180 top locked
LED114 "WS2812B-2020-V6" LED-SMD_4P-L2.2-W2.0-P1.00_WS2815C-2020-4P 6847.29,6024.98 r180 top locked
LED115 "WS2812B-2020-V6" LED-SMD_4P-L2.2-W2.0-P1.00_WS2815C-2020-4P 6097.29,6024.98 r180 top locked
LED116 "WS2812B-2020-V6" LED-SMD_4P-L2.2-W2.0-P1.00_WS2815C-2020-4P 5347.29,6024.98 r180 top locked
LED117 "WS2812B-2020-V6" LED-SMD_4P-L2.2-W2.0-P1.00_WS2815C-2020-4P 4282.29,6024.98 r180 top locked
LED118 "WS2812B-2020-V6" LED-SMD_4P-L2.2-W2.0-P1.00_WS2815C-2020-4P 3532.29,6024.98 r180 top locked
LED119 "WS2812B-2020-V6" LED-SMD_4P-L2.2-W2.0-P1.00_WS2815C-2020-4P 7597.29,5274.98 r180 top locked
LED120 "WS2812B-2020-V6" LED-SMD_4P-L2.2-W2.0-P1.00_WS2815C-2020-4P 6847.29,5274.98 r180 top locked
LED121 "WS2812B-2020-V6" LED-SMD_4P-L2.2-W2.0-P1.00_WS2815C-2020-4P 6097.29,5274.98 r180 top locked
LED122 "WS2812B-2020-V6" LED-SMD_4P-L2.2-W2.0-P1.00_WS2815C-2020-4P 5347.29,5274.98 r180 top locked
LED123 "WS2812B-2020-V6" LED-SMD_4P-L2.2-W2.0-P1.00_WS2815C-2020-4P 4282.29,5274.98 r180 top locked
LED124 "WS2812B-2020-V6" LED-SMD_4P-L2.2-W2.0-P1.00_WS2815C-2020-4P 3532.29,5274.98 r180 top locked
LED125 "WS2812B-2020-V6" LED-SMD_4P-L2.2-W2.0-P1.00_WS2815C-2020-4P 7597.29,4524.98 r180 top locked
LED126 "WS2812B-2020-V6" LED-SMD_4P-L2.2-W2.0-P1.00_WS2815C-2020-4P 6847.29,4524.98 r180 top locked
LED127 "WS2812B-2020-V6" LED-SMD_4P-L2.2-W2.0-P1.00_WS2815C-2020-4P 6097.29,4524.98 r180 top locked
LED128 "WS2812B-2020-V6" LED-SMD_4P-L2.2-W2.0-P1.00_WS2815C-2020-4P 5347.29,4524.98 r180 top locked
LED129 "WS2812B-2020-V6" LED-SMD_4P-L2.2-W2.0-P1.00_WS2815C-2020-4P 4282.29,4524.98 r180 top locked
LED130 "WS2812B-2020-V6" LED-SMD_4P-L2.2-W2.0-P1.00_WS2815C-2020-4P 3532.29,4524.98 r180 top locked
LED131 "WS2812B-2020-V6" LED-SMD_4P-L2.2-W2.0-P1.00_WS2815C-2020-4P 10912.29,10089.98 r180 top locked
LED132 "WS2812B-2020-V6" LED-SMD_4P-L2.2-W2.0-P1.00_WS2815C-2020-4P 10912.29,9339.98 r180 top locked
LED133 "WS2812B-2020-V6" LED-SMD_4P-L2.2-W2.0-P1.00_WS2815C-2020-4P 10912.29,8589.98 r180 top locked
LED134 "WS2812B-2020-V6" LED-SMD_4P-L2.2-W2.0-P1.00_WS2815C-2020-4P 10912.29,7839.98 r180 top locked
LED135 "WS2812B-2020-V6" LED-SMD_4P-L2.2-W2.0-P1.00_WS2815C-2020-4P 9787.29,10089.98 r180 top locked
LED136 "WS2812B-2020-V6" LED-SMD_4P-L2.2-W2.0-P1.00_WS2815C-2020-4P 9787.29,9339.98 r180 top locked
LED137 "WS2812B-2020-V6" LED-SMD_4P-L2.2-W2.0-P1.00_WS2815C-2020-4P 9787.29,8589.98 r180 top locked
LED138 "WS2812B-2020-V6" LED-SMD_4P-L2.2-W2.0-P1.00_WS2815C-2020-4P 9787.29,7839.98 r180 top locked
LED139 "WS2812B-2020-V6" LED-SMD_4P-L2.2-W2.0-P1.00_WS2815C-2020-4P 8662.29,10089.98 r180 top locked
LED141 "WS2812B-2020-V6" LED-SMD_4P-L2.2-W2.0-P1.00_WS2815C-2020-4P 8662.29,8964.98 r180 top locked
LED142 "WS2812B-2020-V6" LED-SMD_4P-L2.2-W2.0-P1.00_WS2815C-2020-4P 8662.29,7839.98 r180 top locked
LED143 "WS2812B-2020-V6" LED-SMD_4P-L2.2-W2.0-P1.00_WS2815C-2020-4P 8662.29,6774.98 r180 top locked
LED144 "WS2812B-2020-V6" LED-SMD_4P-L2.2-W2.0-P1.00_WS2815C-2020-4P 9412.29,6774.98 r180 top locked
LED145 "WS2812B-2020-V6" LED-SMD_4P-L2.2-W2.0-P1.00_WS2815C-2020-4P 10162.29,6774.98 r180 top locked
LED146 "WS2812B-2020-V6" LED-SMD_4P-L2.2-W2.0-P1.00_WS2815C-2020-4P 8662.29,4899.98 r180 top locked
LED147 "WS2812B-2020-V6" LED-SMD_4P-L2.2-W2.0-P1.00_WS2815C-2020-4P 9412.29,4899.98 r180 top locked
LED148 "WS2812B-2020-V6" LED-SMD_4P-L2.2-W2.0-P1.00_WS2815C-2020-4P 10162.29,4899.98 r180 top locked
LED149 "WS2812B-2020-V6" LED-SMD_4P-L2.2-W2.0-P1.00_WS2815C-2020-4P 12182.92,10546.45 r90 top locked
LED150 "WS2812B-2020-V6" LED-SMD_4P-L2.2-W2.0-P1.00_WS2815C-2020-4P 12182.92,9046.45 r90 top locked
LED151 "WS2812B-2020-V6" LED-SMD_4P-L2.2-W2.0-P1.00_WS2815C-2020-4P 12182.92,7546.45 r90 top locked
LED152 "WS2812B-2020-V6" LED-SMD_4P-L2.2-W2.0-P1.00_WS2815C-2020-4P 12182.92,6046.45 r90 top locked
LED153 "WS2812B-2020-V6" LED-SMD_4P-L2.2-W2.0-P1.00_WS2815C-2020-4P 11602.29,4524.98 r180 top locked
LED154 "WS2812B-2020-V6" LED-SMD_4P-L2.2-W2.0-P1.00_WS2815C-2020-4P 11602.29,5274.98 r180 top locked
LED155 "WS2812B-2020-V6" LED-SMD_4P-L2.2-W2.0-P1.00_WS2815C-2020-4P 11602.29,3774.98 r180 top locked
P1 "2.54-2*8P简牛" IDC-TH_16P-P2.54_C3406 3775,11850 r0 bottom locked
P2 "2.54-2*5P简牛" IDC-TH_10P-P2.54_C5665 3675,3425 r270 bottom locked
P3 "2.54-2*5P简牛" IDC-TH_10P-P2.54_C5665 11973.73,7023.74 r180 bottom locked
R1 "0402WGF1002TCE" R0402 5625,11975 r90 top locked
R2 "0402WGF1002TCE" R0402 5575,11975 r90 top locked
R3 "0402WGF1002TCE" R0402 5525,11975 r90 top locked
R4 "0402WGF1002TCE" R0402 5475,11975 r90 top locked
R5 "0402WGF1002TCE" R0402 5450,11875 r90 top locked
R6 "0402WGF1002TCE" R0402 5500,11875 r90 top locked
R7 "0402WGF1002TCE" R0402 5550,11875 r90 top locked
R8 "0402WGF1002TCE" R0402 5600,11875 r90 top locked
R9 "0402WGF1002TCE" R0402 4625,11875 r90 top locked
R10 "0402WGF1002TCE" R0402 4675,11875 r90 top locked
R11 "0402WGF1002TCE" R0402 4725,11875 r90 top locked
SW1 "MX1A-11NW" SW-TH_MX1A-11NW#1 11977.29,11704.97 r180 top locked
SW2 "MX1A-11NW" SW-TH_MX1A-11NW#1 9412.29,5449.97 r180 top locked
SW3 "MX1A-11NW" SW-TH_MX1A-11NW#1 9412.29,3949.97 r180 top locked
SW4 "MX1A-11NW" SW-TH_MX1A-11NW#1 5347.29,3574.97 r180 top locked
SW5 "MX1A-11NW" SW-TH_MX1A-11NW#1 7222.29,3574.97 r180 top locked
SW63 "MX1A-11NW" SW-TH_MX1A-11NW#1 10912.29,11704.97 r180 top locked
SW64 "MX1A-11NW" SW-TH_MX1A-11NW#1 10912.29,10954.97 r180 top locked
SW65 "MX1A-11NW" SW-TH_MX1A-11NW#1 10162.29,11704.97 r180 top locked
SW66 "MX1A-11NW" SW-TH_MX1A-11NW#1 10162.29,10954.97 r180 top locked
SW67 "MX1A-11NW" SW-TH_MX1A-11NW#1 9412.29,11704.97 r180 top locked
SW68 "MX1A-11NW" SW-TH_MX1A-11NW#1 9412.29,10954.97 r180 top locked
SW69 "MX1A-11NW" SW-TH_MX1A-11NW#1 8662.29,11704.97 r180 top locked
SW70 "MX1A-11NW" SW-TH_MX1A-11NW#1 8662.29,10954.97 r180 top locked
SW71 "MX1A-11NW" SW-TH_MX1A-11NW#1 7600,11700 r180 top locked
SW72 "MX1A-11NW" SW-TH_MX1A-11NW#1 7597.29,10954.97 r180 top locked
SW73 "MX1A-11NW" SW-TH_MX1A-11NW#1 6847.29,11704.97 r180 top locked
SW74 "MX1A-11NW" SW-TH_MX1A-11NW#1 6847.29,10954.97 r180 top locked
SW75 "MX1A-11NW" SW-TH_MX1A-11NW#1 6097.29,11704.97 r180 top locked
SW76 "MX1A-11NW" SW-TH_MX1A-11NW#1 6097.29,10954.97 r180 top locked
SW78 "MX1A-11NW" SW-TH_MX1A-11NW#1 5032.29,10954.97 r180 top locked
SW80 "MX1A-11NW" SW-TH_MX1A-11NW#1 4282.29,10954.97 r180 top locked
SW82 "MX1A-11NW" SW-TH_MX1A-11NW#1 3532.29,10954.97 r180 top locked
SW83 "MX1A-11NW" SW-TH_MX1A-11NW#1 7597.29,9889.97 r180 top locked
SW84 "MX1A-11NW" SW-TH_MX1A-11NW#1 6847.29,9889.97 r180 top locked
SW85 "MX1A-11NW" SW-TH_MX1A-11NW#1 6097.29,9889.97 r180 top locked
SW86 "MX1A-11NW" SW-TH_MX1A-11NW#1 5032.29,9889.97 r180 top locked
SW87 "MX1A-11NW" SW-TH_MX1A-11NW#1 4282.29,9889.97 r180 top locked
SW88 "MX1A-11NW" SW-TH_MX1A-11NW#1 3532.29,9889.97 r180 top locked
SW89 "MX1A-11NW" SW-TH_MX1A-11NW#1 7597.29,9139.97 r180 top locked
SW90 "MX1A-11NW" SW-TH_MX1A-11NW#1 6847.29,9139.97 r180 top locked
SW91 "MX1A-11NW" SW-TH_MX1A-11NW#1 6097.29,9139.97 r180 top locked
SW92 "MX1A-11NW" SW-TH_MX1A-11NW#1 5032.29,9139.97 r180 top locked
SW93 "MX1A-11NW" SW-TH_MX1A-11NW#1 4282.29,9139.97 r180 top locked
SW94 "MX1A-11NW" SW-TH_MX1A-11NW#1 3532.29,9139.97 r180 top locked
SW95 "MX1A-11NW" SW-TH_MX1A-11NW#1 7597.29,8389.97 r180 top locked
SW96 "MX1A-11NW" SW-TH_MX1A-11NW#1 6847.29,8389.97 r180 top locked
SW97 "MX1A-11NW" SW-TH_MX1A-11NW#1 6097.29,8389.97 r180 top locked
SW98 "MX1A-11NW" SW-TH_MX1A-11NW#1 5032.29,8389.97 r180 top locked
SW99 "MX1A-11NW" SW-TH_MX1A-11NW#1 4282.29,8389.97 r180 top locked
SW100 "MX1A-11NW" SW-TH_MX1A-11NW#1 3532.29,8389.97 r180 top locked
SW101 "MX1A-11NW" SW-TH_MX1A-11NW#1 7597.29,7639.97 r180 top locked
SW102 "MX1A-11NW" SW-TH_MX1A-11NW#1 6847.29,7639.97 r180 top locked
SW103 "MX1A-11NW" SW-TH_MX1A-11NW#1 6097.29,7639.97 r180 top locked
SW104 "MX1A-11NW" SW-TH_MX1A-11NW#1 5032.29,7639.97 r180 top locked
SW105 "MX1A-11NW" SW-TH_MX1A-11NW#1 4282.29,7639.97 r180 top locked
SW106 "MX1A-11NW" SW-TH_MX1A-11NW#1 3532.29,7639.97 r180 top locked
SW107 "MX1A-11NW" SW-TH_MX1A-11NW#1 7597.29,6574.97 r180 top locked
SW108 "MX1A-11NW" SW-TH_MX1A-11NW#1 6847.29,6574.97 r180 top locked
SW109 "MX1A-11NW" SW-TH_MX1A-11NW#1 6097.29,6574.97 r180 top locked
SW110 "MX1A-11NW" SW-TH_MX1A-11NW#1 5347.29,6574.97 r180 top locked
SW111 "MX1A-11NW" SW-TH_MX1A-11NW#1 4282.29,6574.97 r180 top locked
SW112 "MX1A-11NW" SW-TH_MX1A-11NW#1 3532.29,6574.97 r180 top locked
SW113 "MX1A-11NW" SW-TH_MX1A-11NW#1 7597.29,5824.97 r180 top locked
SW114 "MX1A-11NW" SW-TH_MX1A-11NW#1 6847.29,5824.97 r180 top locked
SW115 "MX1A-11NW" SW-TH_MX1A-11NW#1 6097.29,5824.97 r180 top locked
SW116 "MX1A-11NW" SW-TH_MX1A-11NW#1 5347.29,5824.97 r180 top locked
SW117 "MX1A-11NW" SW-TH_MX1A-11NW#1 4282.29,5824.97 r180 top locked
SW118 "MX1A-11NW" SW-TH_MX1A-11NW#1 3532.29,5824.97 r180 top locked
SW119 "MX1A-11NW" SW-TH_MX1A-11NW#1 7597.29,5074.97 r180 top locked
SW120 "MX1A-11NW" SW-TH_MX1A-11NW#1 6847.29,5074.97 r180 top locked
SW121 "MX1A-11NW" SW-TH_MX1A-11NW#1 6097.29,5074.97 r180 top locked
SW122 "MX1A-11NW" SW-TH_MX1A-11NW#1 5347.29,5074.97 r180 top locked
SW123 "MX1A-11NW" SW-TH_MX1A-11NW#1 4282.29,5074.97 r180 top locked
SW124 "MX1A-11NW" SW-TH_MX1A-11NW#1 3532.29,5074.97 r180 top locked
SW125 "MX1A-11NW" SW-TH_MX1A-11NW#1 7597.29,4324.97 r180 top locked
SW126 "MX1A-11NW" SW-TH_MX1A-11NW#1 6847.29,4324.97 r180 top locked
SW127 "MX1A-11NW" SW-TH_MX1A-11NW#1 6097.29,4324.97 r180 top locked
SW128 "MX1A-11NW" SW-TH_MX1A-11NW#1 5347.29,4324.97 r180 top locked
SW129 "MX1A-11NW" SW-TH_MX1A-11NW#1 4282.29,4324.97 r180 top locked
SW130 "MX1A-11NW" SW-TH_MX1A-11NW#1 3532.29,4324.97 r180 top locked
SW131 "MX1A-11NW" SW-TH_MX1A-11NW#1 10912.29,9889.97 r180 top locked
SW132 "MX1A-11NW" SW-TH_MX1A-11NW#1 10912.29,9139.97 r180 top locked
SW133 "MX1A-11NW" SW-TH_MX1A-11NW#1 10912.29,8389.97 r180 top locked
SW134 "MX1A-11NW" SW-TH_MX1A-11NW#1 10912.29,7639.97 r180 top locked
SW135 "MX1A-11NW" SW-TH_MX1A-11NW#1 9787.29,9889.97 r180 top locked
SW136 "MX1A-11NW" SW-TH_MX1A-11NW#1 9787.29,9139.97 r180 top locked
SW137 "MX1A-11NW" SW-TH_MX1A-11NW#1 9787.29,8389.97 r180 top locked
SW138 "MX1A-11NW" SW-TH_MX1A-11NW#1 9787.29,7639.97 r180 top locked
SW139 "MX1A-11NW" SW-TH_MX1A-11NW#1 8662.29,9889.97 r180 top locked
SW141 "MX1A-11NW" SW-TH_MX1A-11NW#1 8662.29,8764.97 r180 top locked
SW142 "MX1A-11NW" SW-TH_MX1A-11NW#1 8662.29,7639.97 r180 top locked
SW143 "MX1A-11NW" SW-TH_MX1A-11NW#1 8662.29,6574.97 r180 top locked
SW144 "MX1A-11NW" SW-TH_MX1A-11NW#1 9412.29,6574.97 r180 top locked
SW145 "MX1A-11NW" SW-TH_MX1A-11NW#1 10162.29,6574.97 r180 top locked
SW146 "MX1A-11NW" SW-TH_MX1A-11NW#1 8662.29,4699.97 r180 top locked
SW147 "MX1A-11NW" SW-TH_MX1A-11NW#1 9412.29,4699.97 r180 top locked
SW148 "MX1A-11NW" SW-TH_MX1A-11NW#1 10162.29,4699.97 r180 top locked
SW149 "MX1A-11NW" SW-TH_MX1A-11NW#2 11982.91,10546.45 r90 top locked
SW150 "MX1A-11NW" SW-TH_MX1A-11NW#2 11982.91,9046.45 r90 top locked
SW151 "MX1A-11NW" SW-TH_MX1A-11NW#2 11982.91,7546.45 r90 top locked
SW152 "MX1A-11NW" SW-TH_MX1A-11NW#2 11982.91,6046.45 r90 top locked
SW153 "MX1A-11NW" SW-TH_MX1A-11NW#1 11602.29,4324.97 r180 top locked
SW154 "MX1A-11NW" SW-TH_MX1A-11NW#1 11602.29,5074.97 r180 top locked
SW155 "MX1A-11NW" SW-TH_MX1A-11NW#1 11602.29,3574.97 r180 top locked
U1 "74HC595D,118" SOIC-16_L9.9-W3.9-P1.27-LS6.0-BL 11450,11600 r0 top locked
U2 "74HC595D,118" SOIC-16_L9.9-W3.9-P1.27-LS6.0-BL 8125,11650 r0 top locked
U3 "74HC165D,653" SOIC-16_L9.9-W3.9-P1.27-LS6.0-BL 5525,11675 r0 top locked
U4 "74HC165D,653" SOIC-16_L9.9-W3.9-P1.27-LS6.0-BL 4650,11675 r0 top locked

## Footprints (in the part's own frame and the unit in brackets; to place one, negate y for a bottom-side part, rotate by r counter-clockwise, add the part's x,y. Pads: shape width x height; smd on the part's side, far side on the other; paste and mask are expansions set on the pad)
C0402 [mm]
  rect 0.5x0.54 smd: 1(-0.42,0) 2(0.42,0)
  silkscreen extent -0.87,-0.5 0.87,0.5
C0805 [mm]
  rect 1.41x1.35 smd: 1(-1,0) 2(1,0)
  silkscreen extent -1.96,-0.9 1.96,0.9
F1812 [mil]
  rect 55.38x137.76 smd: 1(-72.97,0) 2(72.97,0)
  silkscreen extent -110,-80 110,80
IDC-TH_10P-P2.54_C5665 [mil]
  round 60 hole 39.37: 1(-200,-50) 2(-200,50) 3(-100,-50) 4(-100,50) 5(0,-50) 6(0,50) 7(100,-50) 8(100,50) 9(200,-50) 10(200,50)
  silkscreen extent -400,-175 400,173
IDC-TH_16P-P2.54_C3406 [mil]
  round 60 hole 43.3: 1(-350,-50) 2(-350,50) 3(-250,-50) 4(-250,50) 5(-150,-50) 6(-150,50) 7(-50,-50) 8(-50,50) 9(50,-50) 10(50,50) 11(150,-50) 12(150,50) 13(250,-50) 14(250,50) 15(350,-50) 16(350,50)
  silkscreen extent -561,-177 563,178
LED-SMD_4P-L2.2-W2.0-P1.00_WS2815C-2020-4P [mm]
  rect 0.8x0.8 smd: 1(-0.865,0.55) 2(-0.865,-0.55) 3(0.865,-0.55) 4(0.865,0.55)
  silkscreen extent -1,-1.13 2.02,1.13
R0402 [mm]
  rect 0.566x0.54 smd: 1(-0.433,0) 2(0.433,0)
  silkscreen extent -0.94,-0.5 0.94,0.5
SOD-323_L1.8-W1.3-LS2.5-RD [mm]
  rect 1x0.7 smd: 1(-1.172,0) 2(1.172,0)
  silkscreen extent -1.08,-0.8 0.9,0.8
SOIC-16_L9.9-W3.9-P1.27-LS6.0-BL [mil]
  oval 23.7x77.6 smd: 1(-175,-107.7) 2(-125,-107.7) 3(-75,-107.7) 4(-25,-107.7) 5(25,-107.7) 6(75,-107.7) 7(125,-107.7) 8(175,-107.7) 9(175,107.7) 10(125,107.7) 11(75,107.7) 12(25,107.7) 13(-25,107.7) 14(-75,107.7) 15(-125,107.7) 16(-175,107.7)
  silkscreen extent -211,-111 198,60
SW-TH_MX1A-11NW#1 [mm]
  round 2.2 hole 1.5: 1(-3.81,2.54) 2(2.54,5.08)
  Board Outline Layer circle w0.025: c5.08,0 r0.851
  Board Outline Layer circle w0.025: c-5.08,0 r0.851
  Board Outline Layer circle w0.025: c0,0 r2
  Board Outline Layer region: 4.229,0 4.313,0.369 4.549,0.665 4.891,0.83 5.269,0.83 5.611,0.665 5.847,0.369 5.931,0 5.931,0 5.847,-0.369 5.611,-0.665 5.269,-0.83 4.891,-0.83 4.549,-0.665 4.313,-0.369 4.229,0
  Board Outline Layer region: -5.931,0 -5.847,0.369 -5.611,0.665 -5.269,0.83 -4.891,0.83 -4.549,0.665 -4.313,0.369 -4.229,0 -4.229,0 -4.313,-0.369 -4.549,-0.665 -4.891,-0.83 -5.269,-0.83 -5.611,-0.665 -5.847,-0.369 -5.931,0
  Board Outline Layer region: -2,0 -1.802,0.868 -1.247,1.564 -0.445,1.95 0.445,1.95 1.247,1.564 1.802,0.868 2,0 2,0 1.802,-0.868 1.247,-1.564 0.445,-1.95 -0.445,-1.95 -1.247,-1.564 -1.802,-0.868 -2,0
  Multi-Layer board cut-out: 4.229,0 4.313,0.369 4.549,0.665 4.891,0.83 5.269,0.83 5.611,0.665 5.847,0.369 5.931,0 5.931,0 5.847,-0.369 5.611,-0.665 5.269,-0.83 4.891,-0.83 4.549,-0.665 4.313,-0.369 4.229,0
  Multi-Layer board cut-out: -5.931,0 -5.847,0.369 -5.611,0.665 -5.269,0.83 -4.891,0.83 -4.549,0.665 -4.313,0.369 -4.229,0 -4.229,0 -4.313,-0.369 -4.549,-0.665 -4.891,-0.83 -5.269,-0.83 -5.611,-0.665 -5.847,-0.369 -5.931,0
  Multi-Layer board cut-out: -2,0 -1.802,0.868 -1.247,1.564 -0.445,1.95 0.445,1.95 1.247,1.564 1.802,0.868 2,0 2,0 1.802,-0.868 1.247,-1.564 0.445,-1.95 -0.445,-1.95 -1.247,-1.564 -1.802,-0.868 -2,0
  silkscreen extent -7.8,-7.8 7.8,7.8
SW-TH_MX1A-11NW#2 [mm]
  round 2.2 hole 1.5: 1(-3.81,2.54) 2(2.54,5.08)
  Board Outline Layer circle w0.025: c5.08,0 r0.851
  Board Outline Layer circle w0.025: c-5.08,0 r0.851
  Board Outline Layer circle w0.025: c0,0 r2
  Board Outline Layer region: 5.08,-0.851 4.711,-0.767 4.415,-0.531 4.25,-0.189 4.25,0.189 4.415,0.531 4.711,0.767 5.08,0.851 5.08,0.851 5.449,0.767 5.745,0.531 5.91,0.189 5.91,-0.189 5.745,-0.531 5.449,-0.767 5.08,-0.851
  Board Outline Layer region: -5.08,-0.851 -5.449,-0.767 -5.745,-0.531 -5.91,-0.189 -5.91,0.189 -5.745,0.531 -5.449,0.767 -5.08,0.851 -5.08,0.851 -4.711,0.767 -4.415,0.531 -4.25,0.189 -4.25,-0.189 -4.415,-0.531 -4.711,-0.767 -5.08,-0.851
  Board Outline Layer region: 0,-2 -0.868,-1.802 -1.564,-1.247 -1.95,-0.445 -1.95,0.445 -1.564,1.247 -0.868,1.802 0,2 0,2 0.868,1.802 1.564,1.247 1.95,0.445 1.95,-0.445 1.564,-1.247 0.868,-1.802 0,-2
  Multi-Layer board cut-out: 5.08,-0.851 4.711,-0.767 4.415,-0.531 4.25,-0.189 4.25,0.189 4.415,0.531 4.711,0.767 5.08,0.851 5.08,0.851 5.449,0.767 5.745,0.531 5.91,0.189 5.91,-0.189 5.745,-0.531 5.449,-0.767 5.08,-0.851
  Multi-Layer board cut-out: -5.08,-0.851 -5.449,-0.767 -5.745,-0.531 -5.91,-0.189 -5.91,0.189 -5.745,0.531 -5.449,0.767 -5.08,0.851 -5.08,0.851 -4.711,0.767 -4.415,0.531 -4.25,0.189 -4.25,-0.189 -4.415,-0.531 -4.711,-0.767 -5.08,-0.851
  Multi-Layer board cut-out: 0,-2 -0.868,-1.802 -1.564,-1.247 -1.95,-0.445 -1.95,0.445 -1.564,1.247 -0.868,1.802 0,2 0,2 0.868,1.802 1.564,1.247 1.95,0.445 1.95,-0.445 1.564,-1.247 0.868,-1.802 0,-2
  silkscreen extent -7.8,-7.8 7.8,7.8

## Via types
v1: diameter 24.02, hole 12.01, Top Layer to Bottom Layer, 1393 vias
